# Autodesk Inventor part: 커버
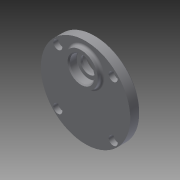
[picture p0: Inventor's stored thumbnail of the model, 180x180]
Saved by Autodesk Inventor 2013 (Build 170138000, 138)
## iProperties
Created: 2015-07
Part Number: 커버
Material: 일반
Document SubType Name: Modeling
Designer: user
Density: 1 g/cm^3
Author: user
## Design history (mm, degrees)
sketch "스케치1"
  geometry: C1 r 40 at (0, 0); 1 further point
  constraints: 1 centre point, 1 coincident
  dimensions: "d0" = 80 diameter of C1
extrude "돌출1" new body sketch "스케치1" distance "d1" = 9; taper "d2" = 0 deg
sketch "스케치2"
  geometry: L1 (0, 0)-(0, 11); L2 (0, 0)-(0, -20); L3 (0, 0)-(20, 0); C1 r 40 at (0, 0) reference; C2 r 14 at (0, 11); C3 r 14 at (0, -20)
  constraints: 6 end point, 2 centre point, 2 coincident, 1 collinear, 1 horizontal, 1 perpendicular, 1 vertical
  dimensions: "d3" = 11 distance of L1.start L1.end; "d4" = 20 distance of L1.start L2.end; "d5" = 90 deg angle of L2 L3 (derived); "d6" = 28 diameter of C2; "d7" = 28 diameter of C3
extrude "돌출2" join sketch "스케치2" distance "d8" = 3; taper "d9" = 0 deg
sketch "스케치3"
  geometry: L1 (0, 0)-(0, 20); L2 (0, 0)-(20, 0); C1 r 40 at (0, 0) reference; C2 r 15 at (0, 20)
  constraints: 4 end point, 1 centre point, 1 coincident, 1 horizontal, 1 perpendicular, 1 vertical
  dimensions: "d10" = 20 distance of L1.start L1.end; "d11" = 90 deg angle of L2 L1 (derived); "d12" = 30 diameter of C2
extrude "돌출3" join sketch "스케치3" distance "d13" = 4; taper "d14" = 0 deg
sketch "스케치4"
  geometry: C1 r 15 at (0, 0) reference; C2 r 7.5 at (0, 0); 1 further point
  constraints: 1 centre point, 1 coincident
  dimensions: "d15" = 15 diameter of C2
extrude "돌출4" cut sketch "스케치4" distance "d16" = 4123; taper "d17" = 0 deg
sketch "스케치5"
  geometry: C1 r 7.5 at (0, 0) reference; C2 r 15 at (0, 0) reference; C3 r 11 at (0, 0); 1 further point
  constraints: 1 centre point, 1 coincident
  dimensions: "d18" = 22 diameter of C3
extrude "돌출5" cut sketch "스케치5" distance "d19" = 7; taper "d20" = 0 deg
sketch "스케치6"
  geometry: C1 r 7.5 at (0, 0) reference; C2 r 14 at (0, 0) reference; C3 r 11 at (0, 0); 1 further point
  constraints: 1 centre point, 1 coincident
  dimensions: "d21" = 22 diameter of C3
extrude "돌출6" cut sketch "스케치6" distance "d22" = 7; taper "d23" = 0 deg
sketch "스케치7"
  geometry: C1 r 14 at (0, 0) reference; C2 r 11 at (0, 0); 1 further point
  constraints: 1 centre point, 1 coincident
  dimensions: "d24" = 22 diameter of C2
extrude "돌출7" cut sketch "스케치7" distance "d25" = 7; taper "d26" = 0 deg
sketch "스케치8"
  geometry: C1 r 9 at (0, 0); 2 further points
  constraints: 1 centre point, 1 coincident, 1 vertical alignment
  dimensions: "d27" = 18 diameter of C1
extrude "돌출8" cut sketch "스케치8" distance "d28" = 1; taper "d29" = 0 deg
chamfer "모따기1" distance "d30" = 1; stored, may be unused: second distance "d31" = 2, angle "d32" = 45 deg
fillet "모깎기1" dims "d33" = 0.3
fillet "모깎기2" dims "d34" = 2
fillet "모깎기4" dims "d36" = 2
sketch "스케치9" dims "d38" = 70
  geometry: L1 (0, 0)-(24.749, 24.749); L2 (0, 0)-(35, 0); C1 r 40 at (0, 0) reference; 4 further points
  constraints: 4 end point, 2 coincident, 1 equal length, 1 horizontal, 8 other
  dimensions: "d39" = 45 deg angle of L2 L1; "d42" = 360 deg dimension on L1.start point (24.749, 24.749) (derived)
hole "구멍1" sketch "스케치9" at (24.749, 24.749), (-24.749, 24.749), (-24.749, -24.749), (24.749, -24.749) diameter "d44" = 4.5; stored, may be unused: countersink angle "d48" = 90 deg, drill point angle "d50" = 118 deg; dims "d45" = 6, "d46" = 8, "d47" = 4.4, "d49" = 8
chamfer "모따기2" distance "d51" = 1; stored, may be unused: second distance "d52" = 2, angle "d53" = 45 deg
node "솔리드1"
